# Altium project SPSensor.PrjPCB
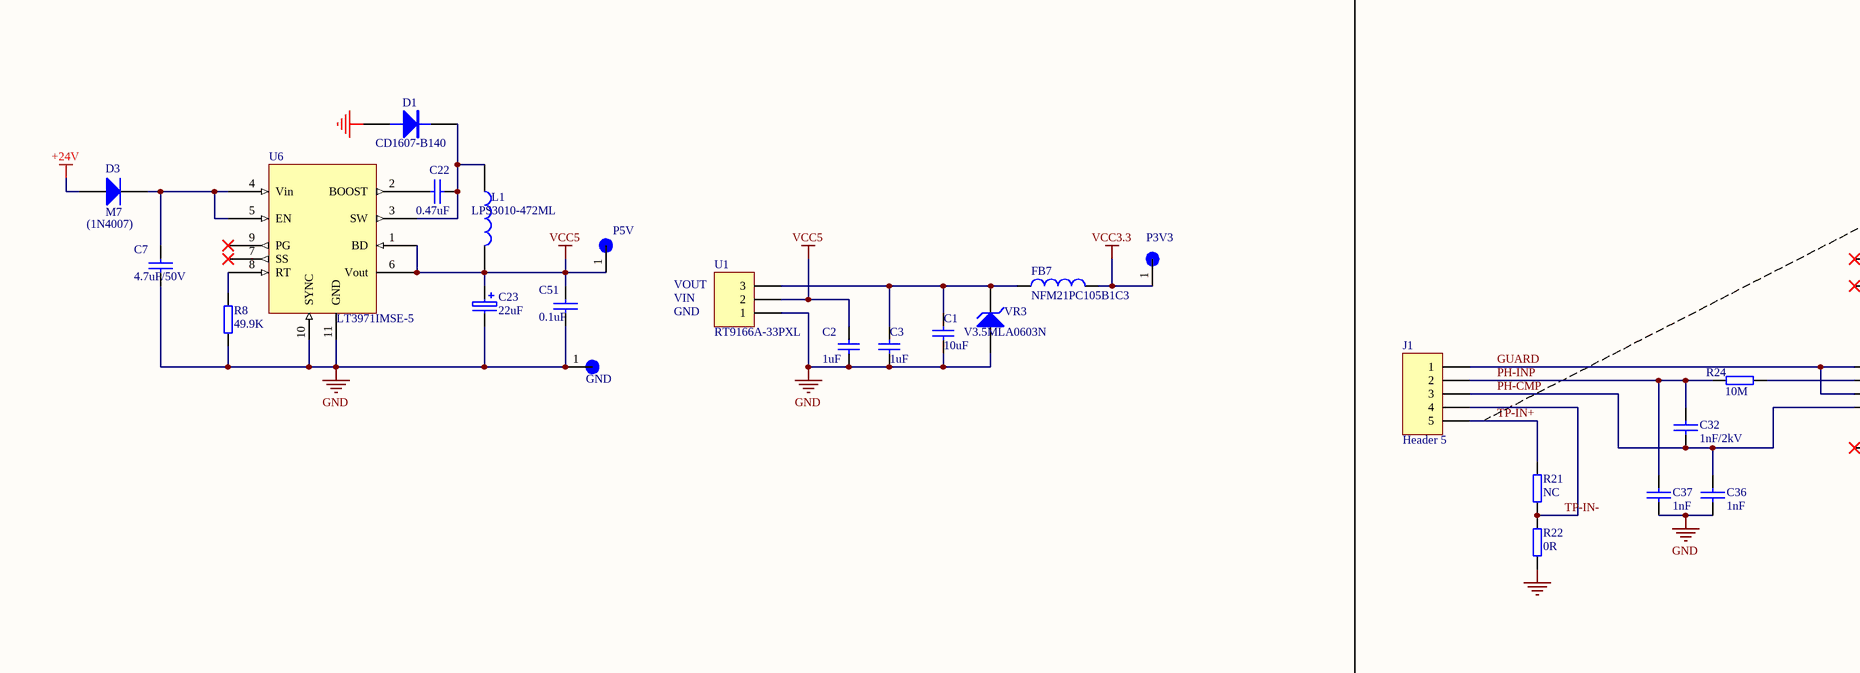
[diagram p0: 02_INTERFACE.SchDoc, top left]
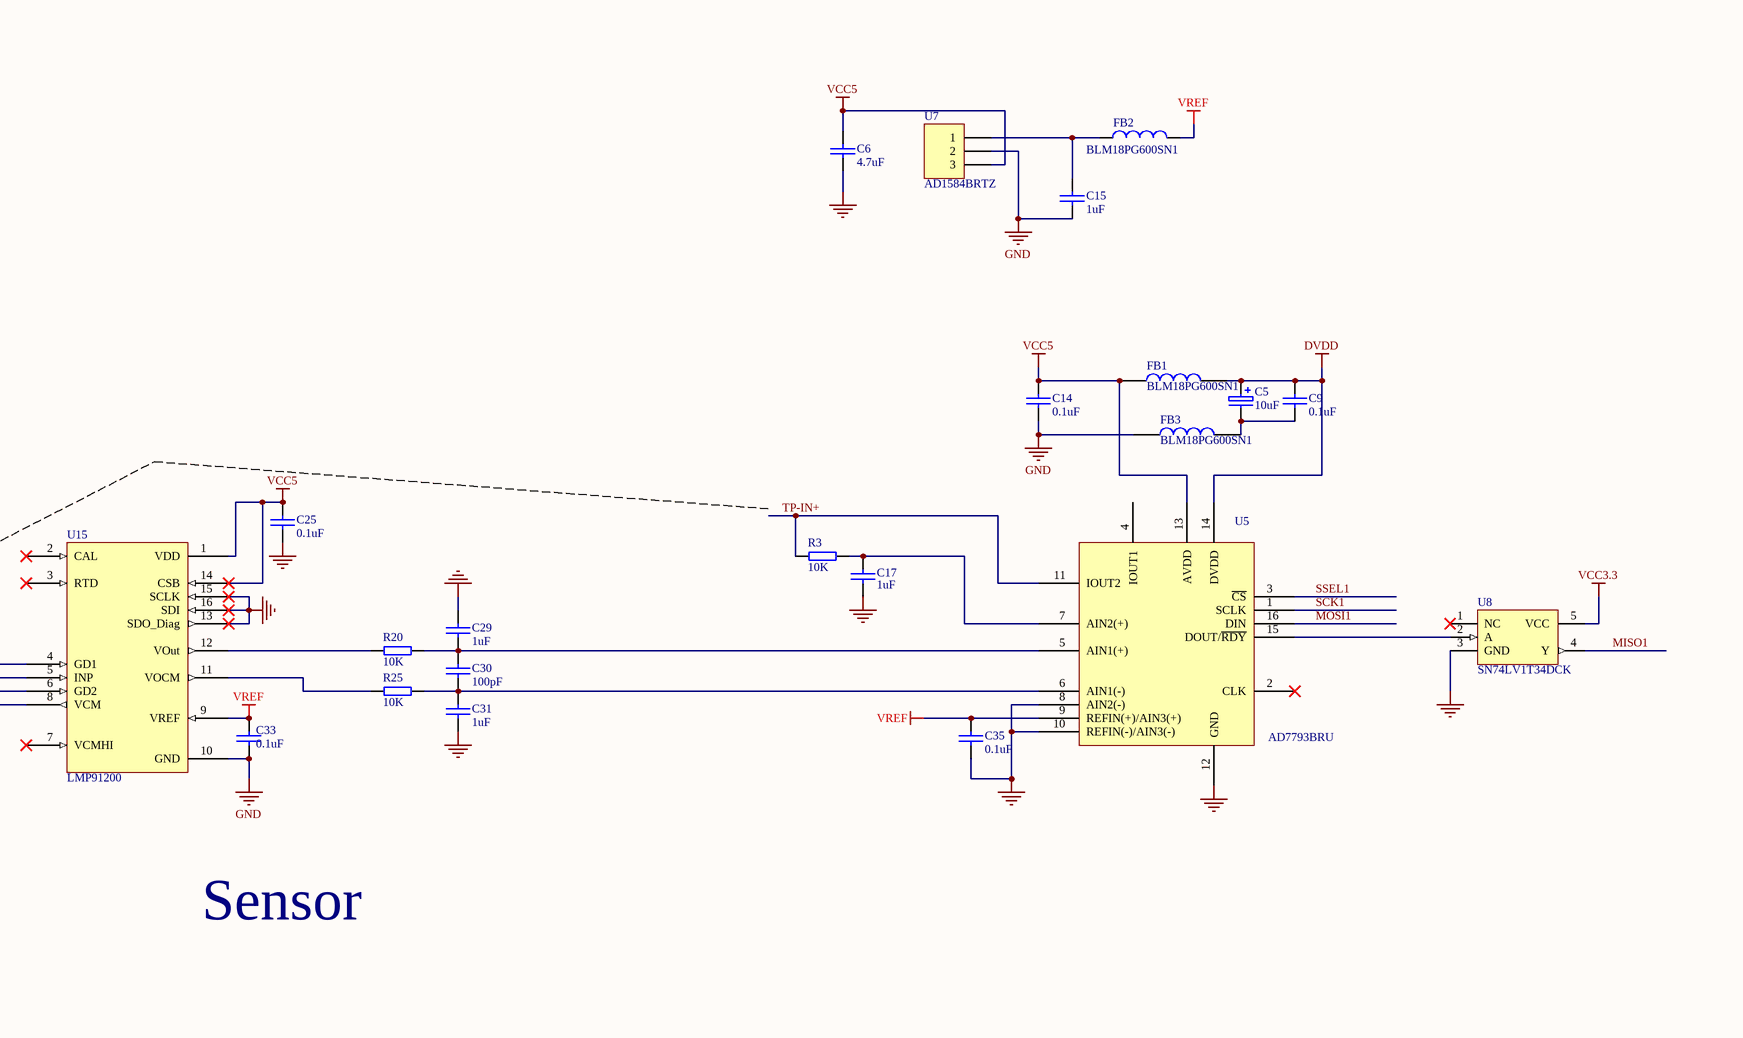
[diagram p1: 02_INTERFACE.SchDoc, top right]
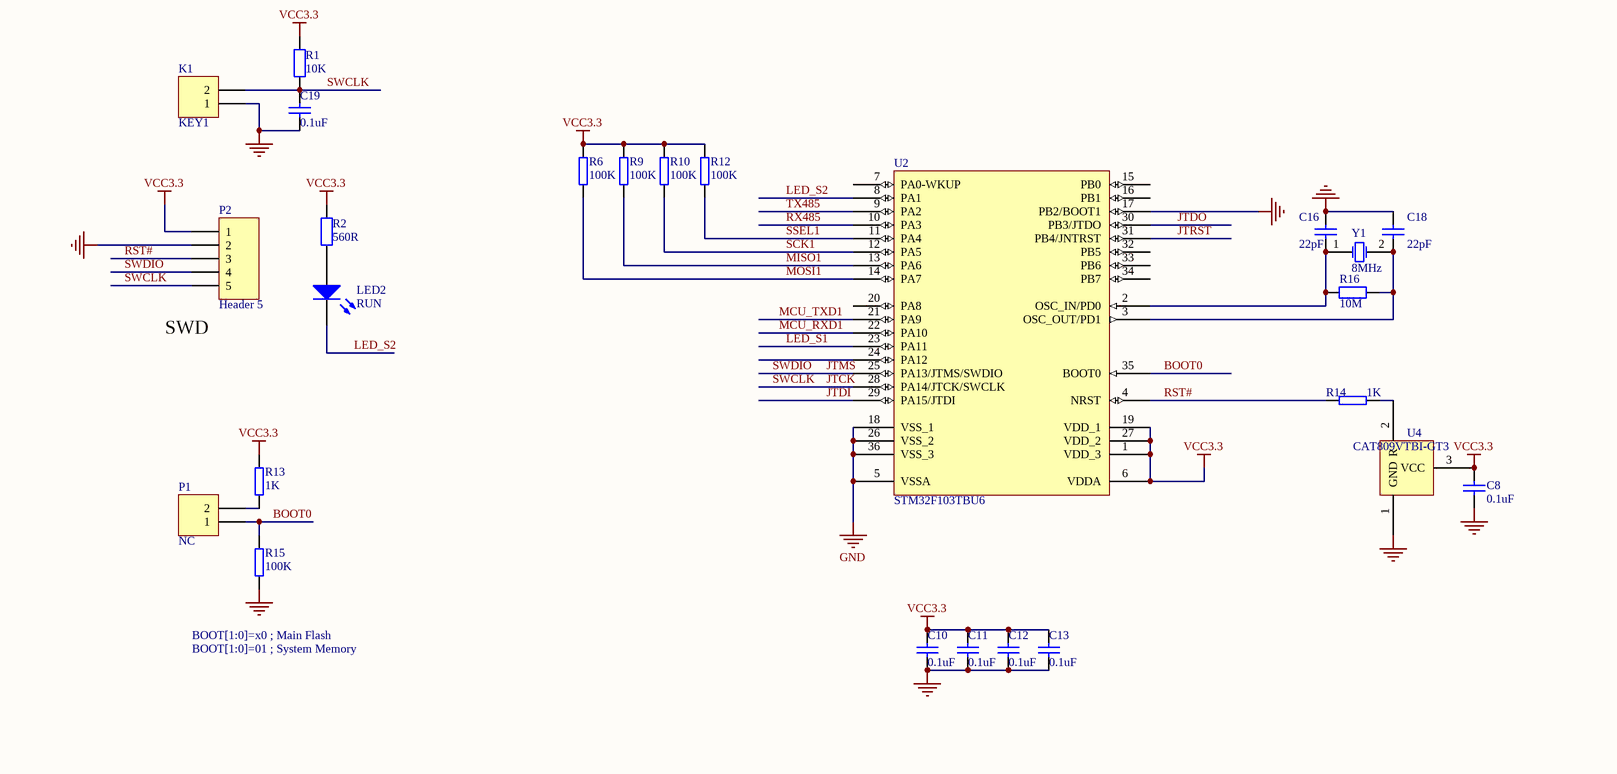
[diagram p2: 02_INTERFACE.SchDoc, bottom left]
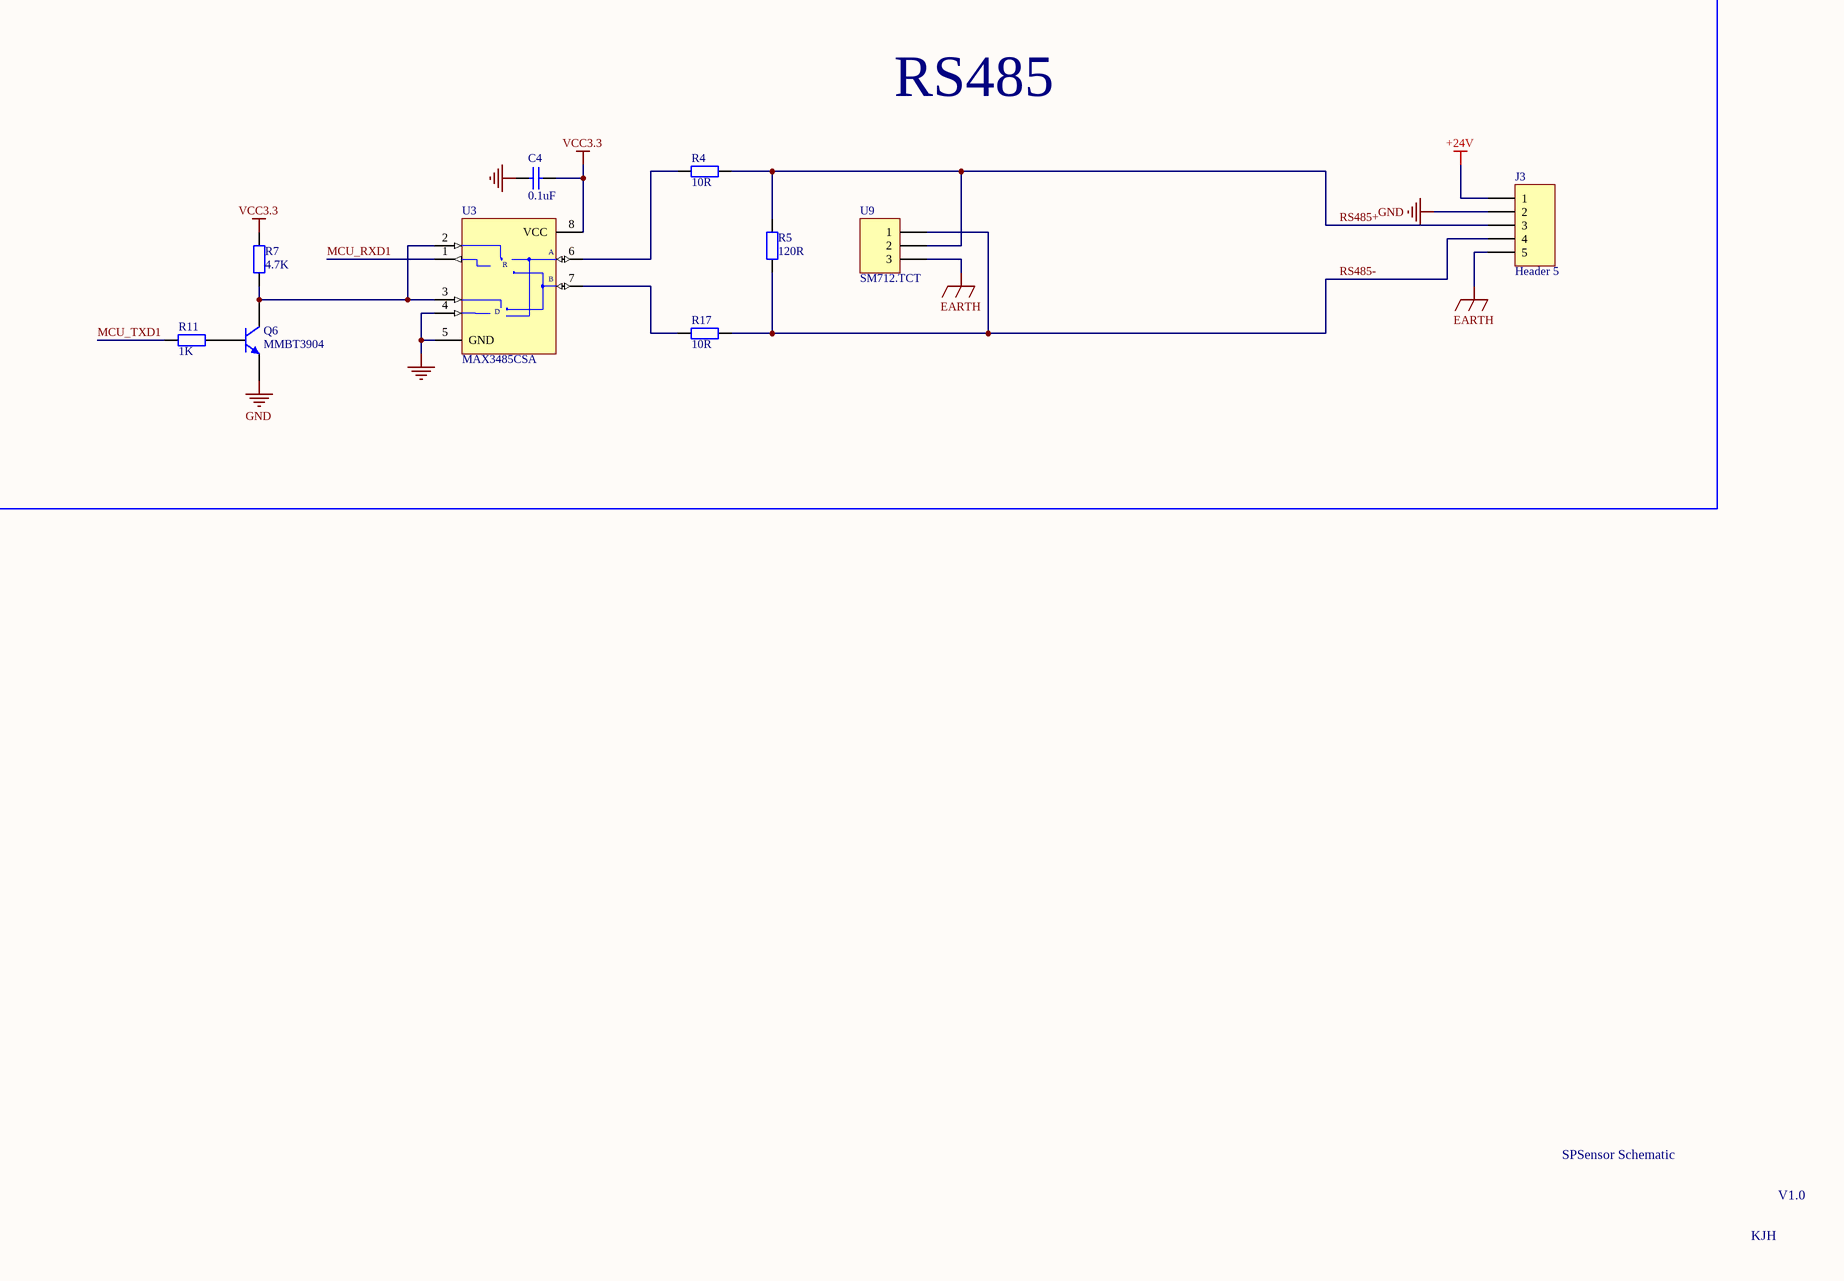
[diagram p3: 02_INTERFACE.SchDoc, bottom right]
1 sheet, 82 parts. Net scope: global (net labels, ports and power ports of the same name join across sheets).
Board file: SPSensor V0.2.PcbDoc

## Sheet 02_INTERFACE.SchDoc
size D; SheetNumber: 0; SheetTotal: 0

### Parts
C1  10uF  [SM1206]
C2  1uF  [SM0603]
C3  1uF  [SM0603]
C4  0.1uF  [SM0603]
C5  10uF  [SM1206]
C6  4.7uF  [SM0603]
C7  4.7uF/50V  [SM1206]
C8  0.1uF  [SM0603]
C9  0.1uF  [SM0603]
C10  0.1uF  [SM0603]
C11  0.1uF  [SM0603]
C12  0.1uF  [SM0603]
C13  0.1uF  [SM0603]
C14  0.1uF  [SM0603]
C15  1uF  [SM0603]
C16  22pF  [SM0603]
C17  1uF  [SM0603]
C18  22pF  [SM0603]
C19  0.1uF  [SM0603]
C22  0.47uF  [SM0603]
C23  22uF  [SM1206]
C25  0.1uF  [SM0603]
C29  1uF  [SM0603]
C30  100pF  [SM0603]
C31  1uF  [SM0603]
C32  1nF/2kV  [SM0805]
C33  0.1uF  [SM0603]
C35  0.1uF  [SM0603]
C36  1nF  [0805A]
C37  1nF  [0805A]
C51  0.1uF  [SM0603]
D1  CD1607-B140  [1206D]
D3  M7  [1206D]
FB1  BLM18PG600SN1  [SM0603]
FB2  BLM18PG600SN1  [SM0603]
FB3  BLM18PG600SN1  [SM0603]
FB7  NFM21PC105B1C3  [NFM21PC105]
GND  TestPoint  [test point]  (value not drawn)
J1  Header 5  [HDR1X5]
J3  Header 5  [HDR1X5]
K1  KEY1  [SM0603]
L1  LPS3010-472ML  [LPS3010]
LED2  RUN  [SM0805]
P1  NC  [SM0603]
P2  Header 5  [HDR1X5]
P3V3  TestPoint  [test point]  (value not drawn)
P5V  TestPoint  [test point]  (value not drawn)
Q6  MMBT3904  [SOT23_N]
R1  10K  [SM0603]
R2  560R  [SM0603]
R3  10K  [SM0603]
R4  10R  [SM0603]
R5  120R  [SM0603]
R6  100K  [SM0603]
R7  4.7K  [SM0603]
R8  49.9K  [SM0603]
R9  100K  [SM0603]
R10  100K  [SM0603]
R11  1K  [SM0603]
R12  100K  [SM0603]
R13  1K  [SM0603]
R14  1K  [SM0603]
R15  100K  [SM0603]
R16  10M  [SM0603]
R17  10R  [SM0603]
R20  10K  [SM0603]
R21  NC  [SM0603]
R22  0R  [SM0603]
R24  10M  [SM0603]
R25  10K  [SM0603]
U1  RT9166A-33PXL  [SOT89L]
U2  STM32F103TBU6  [VFQN36_V]
U3  MAX3485CSA  [NSO8_N]
U4  CAT809VTBI-GT3  [SOT-23]
U5  AD7793BRU  [AD7793]
U6  LT3971IMSE-5  [LT3971]
U7  AD1584BRTZ  [SOT-23]
U8  SN74LV1T34DCK  [SN74LV1T34DCK]
U9  SM712.TCT  [SOT-23]
U15  LMP91200  [LMP91200]
VR3  V3.5MLA0603N  [SM0603]
Y1  8MHz  [CY5.4X4.6]

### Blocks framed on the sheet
Sensor: C5 C6 C9 C14 C15 C17 C25 C29-C33 C35-C37 FB1-FB3 J1 R3 R20-R22 R24 R25 U5 U7 U8 U15
RS485: C4 J3 Q6 R4 R5 R7 R11 R17 U3 U9

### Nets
+24V: D3.1(A) J3.1
DVDD: C5.1 C9.1 FB1.2 U5.14(DVDD)
EARTH: J3.5 U9.3
GND: C1.1 C2.1 C3.1 C4.2 C6.2 C7.2 C8.2 C10.2 C11.2 C12.2 C13.2 C14.2 C15.2 C16.2 C17.2 C18.2 C19.2 C23.2 C25.2 C29.1 C31.2 C33.2 C35.2 C36.2 C37.2 C51.2 D1.1(A) FB3.1 GND.1 J3.2 K1.1 P2.2 Q6.2(E) R8.1 R15.1 R22.1 U1.1 U2.5(VSSA) U2.17(PB2/BOOT1) U2.18(VSS_1) U2.26(VSS_2) U2.36(VSS_3) U3.4(DI) U3.5(GND) U4.1(GND) U5.8(AIN2(-)) U5.10(REFIN(-)/AIN3(-)) U5.12(GND) U6.10(SYNC) U6.11(GND) U7.2 U8.3(GND) U15.10(GND) U15.13(SDO_Diag) U15.15(SCLK) U15.16(SDI) VR3.1(A)
VCC3.3: C4.1 C8.1 C10.1 C11.1 C12.1 C13.1 FB7.2 P2.1 P3V3.1 R1.1 R2.1 R6.1 R7.2 R9.1 R10.1 R12.1 R13.1 U2.1(VDD_3) U2.6(VDDA) U2.19(VDD_1) U2.27(VDD_2) U3.8(VCC) U4.3(VCC) U8.5(VCC)
VCC5: C2.2 C6.1 C14.1 C23.1 C25.1 C51.1 FB1.1 L1.2 P5V.1 U1.2 U5.13(AVDD) U6.1(BD) U6.6(Vout) U7.3 U15.1(VDD) U15.14(CSB)
VREF: C33.1 C35.1 FB2.2 U5.9(REFIN(+)/AIN3(+)) U15.9(VREF)
BOOT0: P1.1 R15.2 U2.35(BOOT0)
GUARD: J1.1 U15.4(GD1) U15.6(GD2)
JTCK: C19.1 K1.2 P2.5 R1.2 U2.28(PA14/JTCK/SWCLK)  [also labelled SWCLK]
JTDI: U2.29(PA15/JTDI)
JTDO: U2.30(PB3/JTDO)
JTMS: P2.4 U2.25(PA13/JTMS/SWDIO)  [also labelled SWDIO]
JTRST: U2.31(PB4/JNTRST)
LED_S1: U2.23(PA11)
LED_S2: LED2.2(K) U2.8(PA1)
MCU_RXD1: U2.22(PA10) U3.1(RO)
MCU_TXD1: R11.1 U2.21(PA9)
MISO1: R9.2 U2.13(PA6) U8.4(Y)
MOSI1: R6.2 U2.14(PA7) U5.16(DIN)
PH-CMP: C32.2 C36.1 J1.3 U15.8(VCM)
PH-INP: C32.1 C37.1 J1.2 R24.1
RS485+: J3.3 R4.1 R5.2 U9.2
RS485-: J3.4 R5.1 R17.1 U9.1
RST#: P2.3 R14.2 U2.4(NRST)
RX485: U2.10(PA3)
SCK1: R10.2 U2.12(PA5) U5.1(SCLK)
SSEL1: R12.2 U2.11(PA4) U5.3(~{CS})
TP-IN+: J1.5 R3.1 R21.2 U5.11(IOUT2)
TP-IN-: J1.4 R21.1 R22.2
TX485: U2.9(PA2)
NetC1_2: C1.2 C3.2 FB7.1 U1.3 VR3.2(K)
NetC5_2: C5.2 C9.2 FB3.2
NetC7_1: C7.1 D3.2(K) U6.4(Vin) U6.5(EN)
NetC15_1: C15.1 FB2.1 U7.1
NetC16_1: C16.1 R16.1 U2.2(OSC_IN/PD0) Y1.1(OSC1)
NetC17_1: C17.1 R3.2 U5.7(AIN2(+))
NetC18_1: C18.1 R16.2 U2.3(OSC_OUT/PD1) Y1.2(OSC2)
NetC22_1: C22.1 U6.2(BOOST)
NetC22_2: C22.2 D1.2(K) L1.1 U6.3(SW)
NetC29_2: C29.2 C30.1 R20.2 U5.5(AIN1(+))
NetC30_2: C30.2 C31.1 R25.2 U5.6(AIN1(-))
NetLED2_1: LED2.1(A) R2.2
NetP1_2: P1.2 R13.2
NetQ6_1: Q6.1(B) R11.2
NetQ6_3: Q6.3(C) R7.1 U3.2(~{RE}) U3.3(DE)
NetR4_2: R4.2 U3.6(A)
NetR8_2: R8.2 U6.8(RT)
NetR14_1: R14.1 U4.2(R)
NetR17_2: R17.2 U3.7(B)
NetR20_1: R20.1 U15.12(VOut)
NetR24_2: R24.2 U15.5(INP)
NetR25_1: R25.1 U15.11(VOCM)
NetU5_15: U5.15(DOUT/~{RDY}) U8.2(A)

Not connected (* = marked no-connect by the designer): U2 7(PA0-WKUP) 15(PB0) 16(PB1) 20(PA8) 24(PA12) 32(PB5) 33(PB6) 34(PB7); U5 2(CLK)* 4(IOUT1); U6 7(SS)* 9(PG)*; U8 1(NC)*; U15 2(CAL)* 3(RTD)* 7(VCMHI)*

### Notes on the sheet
- (1N4007)
- VOUT
- GND
- VIN
- (near P2) SWD
- BOOT[1:0]=x0 ; Main Flash
- BOOT[1:0]=01 ; System Memory
- SPSensor Schematic
- KJH
- V1.0

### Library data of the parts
C1-C3 C16 C18 = Cap: Capacitor; Value: 0.1uF
C4 C8 = Cap: Capacitor, X7R Ceramic
C5 = CAPE: 极性电容
C6 C7 C9 C14 C15 C22 C25 C29-C33 C35-C37 C51 = CAP: Capacitor
C10-C13 C19 = Cap: Capacitor
C17 = CAP: 电容
C23 = C: 极性电容
D1 = DIODE
D3 = Diode 1N4007: 1 Amp General Purpose Rectifier
FB1 FB3 L1 = INDUCTOR
FB2 FB7 = Inductor: Code_IEC: 1005; Value: 10mH
J1 J3 P2 = Header 5: Header, 5-Pin
K1 = Header 2: Header, 2-Pin
LED2 = LED0: Typical INFRARED GaAs LED
P1 = He: Header, 2-Pin, 2.54mm, 排针
Q6 = MMBT3904: NPN Switching Transistor
R1 R2 R4 R5 R7 R16 R17 = Res2: Resistor; Value: 1K
R3 R6 R9 R10 R12 R20-R22 R25 = RES: 电阻
R8 R13-R15 = RE: 电阻
R11 = Res2: Resistor
R24 = R: 电阻
U1 = Header 3: Header, 3-Pin
U2 = STM32F103T8U6: STM32 ARM-based 32-bit MCU with 64 Kbytes Flash, 36-pin VFQFPN, Industrial Temperature
U3 = MAX485CSA: Low-Power, Slew-Rate-Limited RS-485/RS-422 Transceiver
U4 = CA: Onsemi RESET
U5 = AD7793
U6 = LT3971
U7 = Header 3: 4.096V reference
U8 = SN74LV1T34: 1 Channel Level Converter
U9 = Header 3: Asymmerical TVS Diode for RS485
VR3 = D Zener: Zener Diode
Y1 = XTAL: Crystal Oscillator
